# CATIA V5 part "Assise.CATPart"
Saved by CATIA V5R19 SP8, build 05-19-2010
Part number: Assise
Material "Cuir brun": density 945 kg/m3
Bounding box of the stored display mesh (mm): x -169.857 to 163.654, y 114.512 to 494.74, z 599.432 to 902.101
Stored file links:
  G:\EU_thinkMotion\CFAO_2010\MMS_groupe2\MMS_groupe2\OK\nrosalie\nrosalie_cfao_support_d_arme_legere_final\Assise.CATPart
  G:\EU_thinkMotion\CFAO_2010\MMS_groupe2\MMS_groupe2\OK\nrosalie\nrosalie_cfao_support_d_arme_legere_final\Axe_siege.CATPart
  C:\Program Files\Dassault Systemes\B19\intel_a\startup\materials\darkbrown_leather.jpg
  G:\EU_thinkMotion\CFAO_2010\MMS_groupe2\MMS_groupe2\OK\nrosalie\nrosalie_cfao_support_d_arme_legere_final\nrosalie_Support_d_arme_legere.CATProduct
  G:\EU_thinkMotion\CFAO_2010\MMS_groupe2\MMS_groupe2\OK\nrosalie\nrosalie_cfao_support_d_arme_legere_final\Squelette_Colone.CATPart
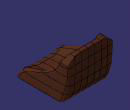
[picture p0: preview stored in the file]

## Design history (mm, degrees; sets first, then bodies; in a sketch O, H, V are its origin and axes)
Set1
  DatumPoint1: linked copy from another document
Body1 (main body)
  DesSubdivisionFeature1 "CATDesSubdivFeatureName"
  Point1: type OnCurve, Support edge [face of DesSubdivisionFeature1 | face of DesSubdivisionFeature1], Length 97.936
  Point2: type OnCurve, Support edge [face of DesSubdivisionFeature1 | face of DesSubdivisionFeature1], Length 263.083
  Point3: type OnCurve, Support edge [face of DesSubdivisionFeature1 | face of DesSubdivisionFeature1], Length 102.41
  Plane1: type 3Points, Element1 Point1, Element2 Point3, Element3 Point2
  Sketch1 on Plane1, origin (0.0074, 0.3147, 599.6104), H (0.9997, -0.0236, 0), V (-0.0236, -0.9997, 0.0005)
    circle A1 centre (-7.0671, -299.6017) radius 41.0729
  Pad1: profile Sketch1, direction (0, 0.0005, 1), length 5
